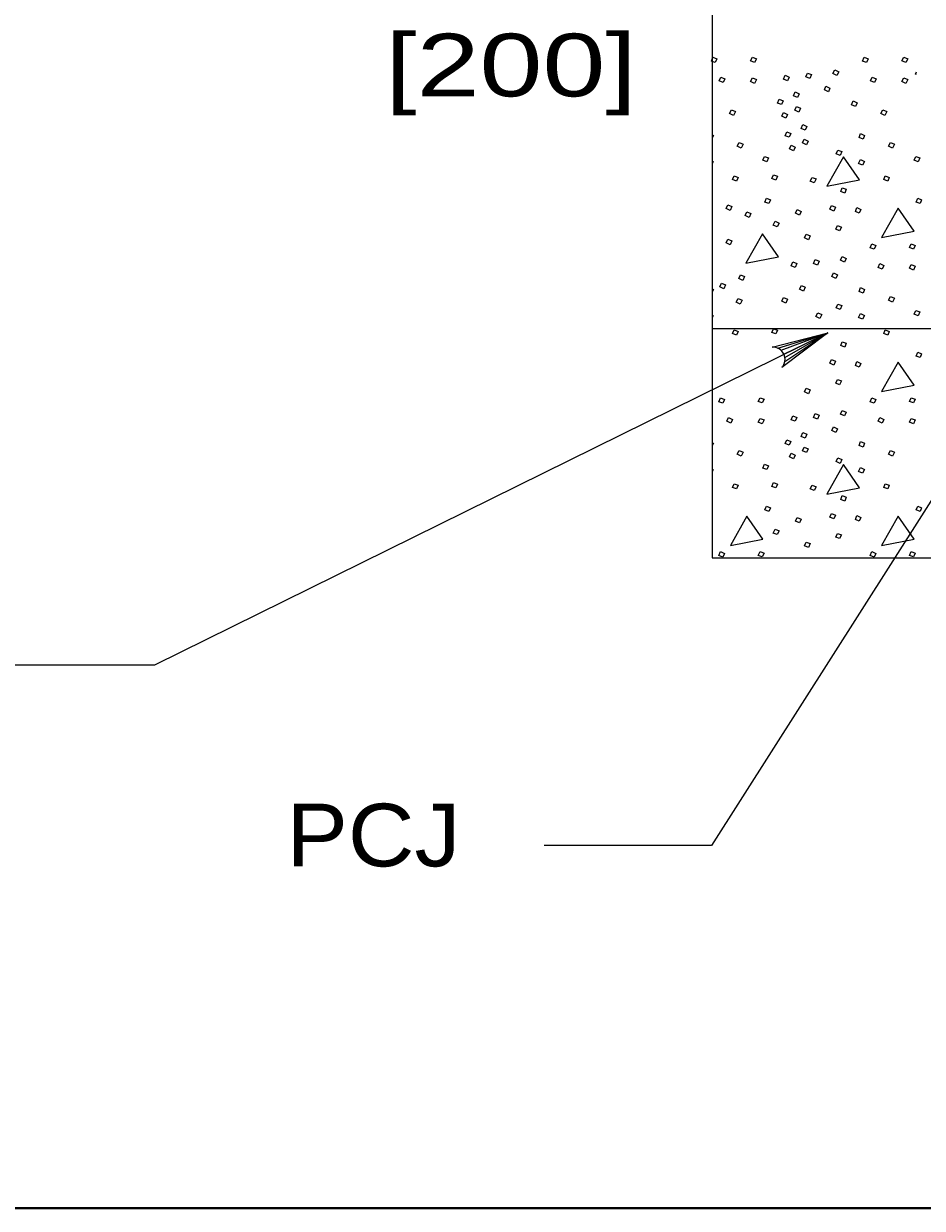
# Model space of a CAD drawing. Extents: x -1431.2 to -1397.2, y -1045.1 to -1001.1.
# Drawn here: x -1422.47 to -1420.193, y -1022.58 to -1019.579 of the extents above; entities that cross this region are included whole.
import ezdxf
from ezdxf.enums import TextEntityAlignment as Align

# ---------------------------------------------------------------- set-up
doc = ezdxf.new("R2010")
doc.units = 0
doc.header["$LTSCALE"] = 0.064
doc.layers.add('1', color=7, linetype='Continuous', lineweight=13)

msp = doc.modelspace()

# ---------------------------------------------------------------- linework, layer by layer
at = {"layer": '1', "lineweight": 25}
msp.add_line((-1420.72517, -1020.351), (-1417.26308, -1020.351), dxfattribs=at)
at = {"layer": '1'}
for p in [(-1420.55892, -1020.40108), (-1420.55083, -1020.40642), (-1420.54367, -1020.41592), (-1420.54092, -1020.42467), (-1420.54092, -1020.43467)]:
    msp.add_line(p, (-1420.4325, -1020.36192), dxfattribs=at)
at = {"layer": '1', "lineweight": 25}
for points in [[(-1397.74575, -1022.57983), (-1429.24575, -1022.57983), (-1429.24575, -1001.57983)], [(-1420.18825, -1017.19833), (-1420.72517, -1017.19833), (-1420.72517, -1020.93208), (-1417.26308, -1020.93208), (-1417.26308, -1017.19833)]]:
    msp.add_lwpolyline(points, dxfattribs=at)
at = {"layer": '1', "lineweight": 40}
msp.add_lwpolyline([(-1429.24575, -1001.57983), (-1397.74575, -1001.57983), (-1397.74575, -1022.57983), (-1429.24575, -1022.57983)], close=True, dxfattribs=at)
at = {"layer": '1'}
for points in [[(-1420.7235, -1019.66375), (-1420.71342, -1019.66842), (-1420.71742, -1019.67783), (-1420.7275, -1019.67383)], [(-1420.62325, -1019.66375), (-1420.61317, -1019.66775), (-1420.61792, -1019.67717), (-1420.628, -1019.67317)], [(-1420.34017, -1019.66375), (-1420.33008, -1019.66842), (-1420.33417, -1019.67783), (-1420.34425, -1019.67383)], [(-1420.24, -1019.66375), (-1420.22992, -1019.66775), (-1420.23458, -1019.67717), (-1420.24475, -1019.67317)], [(-1420.41483, -1019.696), (-1420.40475, -1019.70075), (-1420.40942, -1019.71008), (-1420.4195, -1019.70542)], [(-1420.70333, -1019.71417), (-1420.69325, -1019.71883), (-1420.69725, -1019.72825), (-1420.70733, -1019.72358)], [(-1420.62325, -1019.71617), (-1420.61317, -1019.72017), (-1420.61792, -1019.73033), (-1420.628, -1019.72558)], [(-1420.54058, -1019.70942), (-1420.5305, -1019.71417), (-1420.5345, -1019.72358), (-1420.54458, -1019.7195)], [(-1420.48342, -1019.70408), (-1420.47333, -1019.70808), (-1420.47808, -1019.71817), (-1420.48817, -1019.7135)], [(-1420.32, -1019.71417), (-1420.30992, -1019.71883), (-1420.314, -1019.72825), (-1420.32408, -1019.72358)], [(-1420.24, -1019.71617), (-1420.22992, -1019.72017), (-1420.23458, -1019.73033), (-1420.24475, -1019.72558)], [(-1420.515, -1019.75183), (-1420.50492, -1019.7565), (-1420.509, -1019.76592), (-1420.51908, -1019.76192)], [(-1420.437, -1019.73767), (-1420.42692, -1019.74242), (-1420.431, -1019.75183), (-1420.44108, -1019.74708)], [(-1420.55533, -1019.77067), (-1420.54525, -1019.77467), (-1420.54933, -1019.78408), (-1420.55942, -1019.78008)], [(-1420.51167, -1019.78875), (-1420.50158, -1019.7935), (-1420.50558, -1019.80292), (-1420.51567, -1019.79817)], [(-1420.36842, -1019.77467), (-1420.35833, -1019.77942), (-1420.36242, -1019.78875), (-1420.3725, -1019.78475)], [(-1420.67642, -1019.7975), (-1420.66633, -1019.80158), (-1420.671, -1019.81167), (-1420.68108, -1019.80692)], [(-1420.54458, -1019.80425), (-1420.5345, -1019.80892), (-1420.53858, -1019.81833), (-1420.54867, -1019.81367)], [(-1420.29317, -1019.7975), (-1420.283, -1019.80158), (-1420.28775, -1019.81167), (-1420.29783, -1019.80692)], [(-1420.49575, -1019.83467), (-1420.48567, -1019.83933), (-1420.48967, -1019.84875), (-1420.49983, -1019.84475)], [(-1420.53608, -1019.85342), (-1420.526, -1019.8575), (-1420.53008, -1019.86692), (-1420.54017, -1019.86283)], [(-1420.49242, -1019.87158), (-1420.48233, -1019.87633), (-1420.48633, -1019.88575), (-1420.49642, -1019.881)], [(-1420.34917, -1019.8575), (-1420.33908, -1019.86217), (-1420.34308, -1019.87158), (-1420.35317, -1019.86758)], [(-1420.65717, -1019.88033), (-1420.64708, -1019.88442), (-1420.65175, -1019.8945), (-1420.66183, -1019.88975)], [(-1420.52533, -1019.88708), (-1420.51525, -1019.89175), (-1420.51933, -1019.90117), (-1420.52942, -1019.8965)], [(-1420.407, -1019.89917), (-1420.39692, -1019.90317), (-1420.40092, -1019.91325), (-1420.411, -1019.90858)], [(-1420.27383, -1019.88033), (-1420.26375, -1019.88442), (-1420.2685, -1019.8945), (-1420.27858, -1019.88975)], [(-1420.59258, -1019.91533), (-1420.5825, -1019.91933), (-1420.5865, -1019.92875), (-1420.59658, -1019.92475)], [(-1420.39292, -1019.916), (-1420.43458, -1019.99058), (-1420.35183, -1019.9745)], [(-1420.34983, -1019.92342), (-1420.33975, -1019.92808), (-1420.3445, -1019.9375), (-1420.35458, -1019.9335)], [(-1420.20933, -1019.91533), (-1420.19925, -1019.91933), (-1420.20325, -1019.92875), (-1420.21333, -1019.92475)], [(-1420.66992, -1019.96442), (-1420.65983, -1019.96842), (-1420.66383, -1019.97783), (-1420.67392, -1019.97383)], [(-1420.56975, -1019.96167), (-1420.55967, -1019.96575), (-1420.56433, -1019.97517), (-1420.57442, -1019.97108)], [(-1420.47225, -1019.96842), (-1420.46217, -1019.97242), (-1420.46683, -1019.98183), (-1420.47692, -1019.97783)], [(-1420.28667, -1019.96442), (-1420.27658, -1019.96842), (-1420.28058, -1019.97783), (-1420.29067, -1019.97383)], [(-1420.39558, -1019.99467), (-1420.3855, -1019.99867), (-1420.3895, -1020.00875), (-1420.39958, -1020.00408)], [(-1420.58792, -1020.0215), (-1420.57783, -1020.02558), (-1420.58183, -1020.035), (-1420.59192, -1020.03092)], [(-1420.20458, -1020.0215), (-1420.1945, -1020.02558), (-1420.19858, -1020.035), (-1420.20867, -1020.03092)], [(-1420.68542, -1020.03792), (-1420.67533, -1020.04192), (-1420.68008, -1020.052), (-1420.69017, -1020.04733)], [(-1420.63733, -1020.056), (-1420.62725, -1020.06), (-1420.63192, -1020.07008), (-1420.642, -1020.06533)], [(-1420.50992, -1020.04975), (-1420.49983, -1020.0545), (-1420.50383, -1020.06392), (-1420.51392, -1020.05917)], [(-1420.42317, -1020.03967), (-1420.41308, -1020.04375), (-1420.41708, -1020.05383), (-1420.42717, -1020.04908)], [(-1420.35858, -1020.04508), (-1420.3485, -1020.04975), (-1420.3525, -1020.05917), (-1420.36258, -1020.05517)], [(-1420.25433, -1020.04642), (-1420.29608, -1020.12108), (-1420.21333, -1020.10492)], [(-1420.56567, -1020.07933), (-1420.55558, -1020.08408), (-1420.56033, -1020.0935), (-1420.57042, -1020.08942)], [(-1420.40767, -1020.09008), (-1420.39758, -1020.09417), (-1420.40233, -1020.10358), (-1420.41242, -1020.0995)], [(-1420.59808, -1020.1115), (-1420.63975, -1020.18608), (-1420.55708, -1020.17)], [(-1420.487, -1020.11233), (-1420.47692, -1020.11633), (-1420.481, -1020.12642), (-1420.49108, -1020.12175)], [(-1420.68542, -1020.12517), (-1420.67533, -1020.12917), (-1420.68008, -1020.13925), (-1420.69017, -1020.13458)], [(-1420.32092, -1020.1365), (-1420.31083, -1020.14125), (-1420.31492, -1020.15067), (-1420.325, -1020.14658)], [(-1420.22075, -1020.1365), (-1420.21067, -1020.14058), (-1420.21533, -1020.14992), (-1420.22542, -1020.14592)], [(-1420.46417, -1020.17683), (-1420.45408, -1020.18092), (-1420.45875, -1020.191), (-1420.46883, -1020.18625)], [(-1420.39558, -1020.16875), (-1420.3855, -1020.1735), (-1420.39017, -1020.18292), (-1420.40025, -1020.17817)], [(-1420.52133, -1020.18225), (-1420.51125, -1020.18692), (-1420.51525, -1020.19633), (-1420.52533, -1020.19233)], [(-1420.30075, -1020.18692), (-1420.29067, -1020.19167), (-1420.29467, -1020.20108), (-1420.30475, -1020.19633)], [(-1420.22075, -1020.18892), (-1420.21067, -1020.193), (-1420.21533, -1020.20308), (-1420.22542, -1020.19833)], [(-1420.7015, -1020.23642), (-1420.69142, -1020.24042), (-1420.69608, -1020.2505), (-1420.70617, -1020.24583)], [(-1420.65333, -1020.21533), (-1420.64325, -1020.21942), (-1420.648, -1020.2295), (-1420.65808, -1020.22475)], [(-1420.41775, -1020.2105), (-1420.40767, -1020.21517), (-1420.41167, -1020.22458), (-1420.42183, -1020.21992)], [(-1420.49942, -1020.24242), (-1420.48933, -1020.2465), (-1420.49408, -1020.25658), (-1420.50417, -1020.25183)], [(-1420.34917, -1020.24742), (-1420.33908, -1020.25217), (-1420.34308, -1020.26158), (-1420.35317, -1020.2575)], [(-1420.65975, -1020.2755), (-1420.64967, -1020.27958), (-1420.65442, -1020.28967), (-1420.6645, -1020.28492)], [(-1420.54433, -1020.2725), (-1420.53425, -1020.27658), (-1420.539, -1020.28667), (-1420.54908, -1020.28192)], [(-1420.407, -1020.28917), (-1420.39692, -1020.29317), (-1420.40092, -1020.30325), (-1420.411, -1020.29858)], [(-1420.27383, -1020.27033), (-1420.26375, -1020.27433), (-1420.2685, -1020.28442), (-1420.27858, -1020.27975)], [(-1420.45775, -1020.31158), (-1420.44767, -1020.31567), (-1420.45242, -1020.32575), (-1420.4625, -1020.321)], [(-1420.34983, -1020.31333), (-1420.33975, -1020.31808), (-1420.3445, -1020.32742), (-1420.35458, -1020.32342)], [(-1420.20933, -1020.30525), (-1420.19925, -1020.30933), (-1420.20325, -1020.31875), (-1420.21333, -1020.31467)], [(-1420.66992, -1020.35433), (-1420.65983, -1020.35842), (-1420.66383, -1020.36783), (-1420.67392, -1020.36375)], [(-1420.56975, -1020.35167), (-1420.55967, -1020.35567), (-1420.56433, -1020.36508), (-1420.57442, -1020.36108)], [(-1420.28667, -1020.35433), (-1420.27658, -1020.35842), (-1420.28058, -1020.36783), (-1420.29067, -1020.36375)], [(-1420.39558, -1020.38458), (-1420.3855, -1020.38867), (-1420.3895, -1020.39875), (-1420.39958, -1020.394)], [(-1420.20458, -1020.4115), (-1420.1945, -1020.4155), (-1420.19858, -1020.42492), (-1420.20867, -1020.42092)], [(-1420.42317, -1020.42967), (-1420.41308, -1020.43367), (-1420.41708, -1020.44375), (-1420.42717, -1020.43908)], [(-1420.35858, -1020.435), (-1420.3485, -1020.43975), (-1420.3525, -1020.44917), (-1420.36258, -1020.44508)], [(-1420.25433, -1020.43642), (-1420.29608, -1020.511), (-1420.21333, -1020.49483)], [(-1420.40767, -1020.48008), (-1420.39758, -1020.48408), (-1420.40233, -1020.4935), (-1420.41242, -1020.4895)], [(-1420.487, -1020.50225), (-1420.47692, -1020.50633), (-1420.481, -1020.51642), (-1420.49108, -1020.51167)], [(-1420.70425, -1020.5265), (-1420.69417, -1020.53117), (-1420.69817, -1020.54058), (-1420.70825, -1020.53658)], [(-1420.604, -1020.5265), (-1420.59392, -1020.5305), (-1420.59867, -1020.53992), (-1420.60875, -1020.53592)], [(-1420.32092, -1020.5265), (-1420.31083, -1020.53117), (-1420.31492, -1020.54058), (-1420.325, -1020.53658)], [(-1420.22075, -1020.5265), (-1420.21067, -1020.5305), (-1420.21533, -1020.53992), (-1420.22542, -1020.53592)], [(-1420.46417, -1020.56683), (-1420.45408, -1020.57083), (-1420.45875, -1020.58092), (-1420.46883, -1020.57625)], [(-1420.39558, -1020.55875), (-1420.3855, -1020.56342), (-1420.39017, -1020.57283), (-1420.40025, -1020.56817)], [(-1420.684, -1020.57692), (-1420.67392, -1020.58158), (-1420.678, -1020.591), (-1420.68808, -1020.58633)], [(-1420.604, -1020.57892), (-1420.59392, -1020.58292), (-1420.59867, -1020.593), (-1420.60875, -1020.58833)], [(-1420.52133, -1020.57217), (-1420.51125, -1020.57692), (-1420.51525, -1020.58633), (-1420.52533, -1020.58225)], [(-1420.30075, -1020.57692), (-1420.29067, -1020.58158), (-1420.29467, -1020.591), (-1420.30475, -1020.58633)], [(-1420.22075, -1020.57892), (-1420.21067, -1020.58292), (-1420.21533, -1020.593), (-1420.22542, -1020.58833)], [(-1420.49575, -1020.61458), (-1420.48567, -1020.61925), (-1420.48967, -1020.62867), (-1420.49983, -1020.62467)], [(-1420.41775, -1020.60042), (-1420.40767, -1020.60517), (-1420.41167, -1020.61458), (-1420.42183, -1020.60983)], [(-1420.65717, -1020.66025), (-1420.64708, -1020.66433), (-1420.65175, -1020.67442), (-1420.66183, -1020.66967)], [(-1420.53608, -1020.63342), (-1420.526, -1020.63742), (-1420.53008, -1020.64683), (-1420.54017, -1020.64283)], [(-1420.49242, -1020.6515), (-1420.48233, -1020.65625), (-1420.48633, -1020.66567), (-1420.49642, -1020.66092)], [(-1420.34917, -1020.63742), (-1420.33908, -1020.64208), (-1420.34308, -1020.6515), (-1420.35317, -1020.6475)], [(-1420.27383, -1020.66025), (-1420.26375, -1020.66433), (-1420.2685, -1020.67442), (-1420.27858, -1020.66967)], [(-1420.52533, -1020.667), (-1420.51525, -1020.67167), (-1420.51933, -1020.68108), (-1420.52942, -1020.67642)], [(-1420.407, -1020.67908), (-1420.39692, -1020.68317), (-1420.40092, -1020.69325), (-1420.411, -1020.6885)], [(-1420.59258, -1020.69525), (-1420.5825, -1020.69925), (-1420.5865, -1020.70867), (-1420.59658, -1020.70467)], [(-1420.39292, -1020.69592), (-1420.43458, -1020.7705), (-1420.35183, -1020.75442)], [(-1420.34983, -1020.70333), (-1420.33975, -1020.708), (-1420.3445, -1020.71742), (-1420.35458, -1020.71342)], [(-1420.66992, -1020.74433), (-1420.65983, -1020.74833), (-1420.66383, -1020.75775), (-1420.67392, -1020.75375)], [(-1420.56975, -1020.74167), (-1420.55967, -1020.74567), (-1420.56433, -1020.75508), (-1420.57442, -1020.75108)], [(-1420.47225, -1020.74833), (-1420.46217, -1020.75242), (-1420.46683, -1020.76183), (-1420.47692, -1020.75775)], [(-1420.28667, -1020.74433), (-1420.27658, -1020.74833), (-1420.28058, -1020.75775), (-1420.29067, -1020.75375)], [(-1420.39558, -1020.77458), (-1420.3855, -1020.77858), (-1420.3895, -1020.78867), (-1420.39958, -1020.784)], [(-1420.58792, -1020.8015), (-1420.57783, -1020.8055), (-1420.58183, -1020.81492), (-1420.59192, -1020.81092)], [(-1420.20458, -1020.8015), (-1420.1945, -1020.8055), (-1420.19858, -1020.81492), (-1420.20867, -1020.81092)], [(-1420.63767, -1020.82633), (-1420.67933, -1020.901), (-1420.59658, -1020.88483)], [(-1420.50992, -1020.82975), (-1420.49983, -1020.83442), (-1420.50383, -1020.84383), (-1420.51392, -1020.83908)], [(-1420.42317, -1020.81958), (-1420.41308, -1020.82367), (-1420.41708, -1020.83375), (-1420.42717, -1020.829)], [(-1420.35858, -1020.825), (-1420.3485, -1020.82975), (-1420.3525, -1020.83908), (-1420.36258, -1020.83508)], [(-1420.25433, -1020.82633), (-1420.29608, -1020.901), (-1420.21333, -1020.88483)], [(-1420.56567, -1020.85925), (-1420.55558, -1020.864), (-1420.56033, -1020.87342), (-1420.57042, -1020.86933)], [(-1420.40767, -1020.87008), (-1420.39758, -1020.87408), (-1420.40233, -1020.8835), (-1420.41242, -1020.8795)], [(-1420.487, -1020.89225), (-1420.47692, -1020.89625), (-1420.481, -1020.90633), (-1420.49108, -1020.90167)], [(-1420.70425, -1020.91642), (-1420.69417, -1020.92117), (-1420.69817, -1020.93058), (-1420.70825, -1020.9265)], [(-1420.604, -1020.91642), (-1420.59392, -1020.9205), (-1420.59867, -1020.92992), (-1420.60875, -1020.92583)], [(-1420.32092, -1020.91642), (-1420.31083, -1020.92117), (-1420.31492, -1020.93058), (-1420.325, -1020.9265)], [(-1420.22075, -1020.91642), (-1420.21067, -1020.9205), (-1420.21533, -1020.92992), (-1420.22542, -1020.92583)]]:
    msp.add_lwpolyline(points, close=True, dxfattribs=at)
for points in [[(-1420.2075, -1019.70783), (-1420.21042, -1019.70667), (-1420.2075, -1019.70092)], [(-1420.72517, -1019.86083), (-1420.72233, -1019.86217), (-1420.72517, -1019.86875)], [(-1420.72517, -1019.92708), (-1420.72308, -1019.92808), (-1420.72517, -1019.93242)], [(-1420.72517, -1020.25083), (-1420.72233, -1020.25217), (-1420.72517, -1020.25875)], [(-1420.72517, -1020.317), (-1420.72308, -1020.31808), (-1420.72517, -1020.32233)], [(-1419.89208, -1020.351), (-1420.7275, -1021.66117), (-1421.15075, -1021.66117)], [(-1420.4325, -1020.36192), (-1422.13833, -1021.204), (-1422.65133, -1021.204)], [(-1420.5735, -1020.39858), (-1420.4325, -1020.36192), (-1420.5485, -1020.45)], [(-1420.72517, -1020.64075), (-1420.72233, -1020.64208), (-1420.72517, -1020.64875)], [(-1420.72517, -1020.707), (-1420.72308, -1020.708), (-1420.72517, -1020.71233)]]:
    msp.add_lwpolyline(points, dxfattribs=at)
msp.add_arc((-1420.57138, -1020.42936), 0.03084, 317.98606, 93.81218, dxfattribs=at)

# ---------------------------------------------------------------- texts
at = {"layer": '1', "width": 1.35}
msp.add_text('[200]', height=0.1588, dxfattribs=at).set_placement((-1421.23521, -1019.76325), align=Align.CENTER)
at = {"layer": '1', "width": 1.1}
msp.add_text('PCJ', height=0.1588, dxfattribs=at).set_placement((-1421.80433, -1021.71375))

doc.saveas('drawing.dxf')
